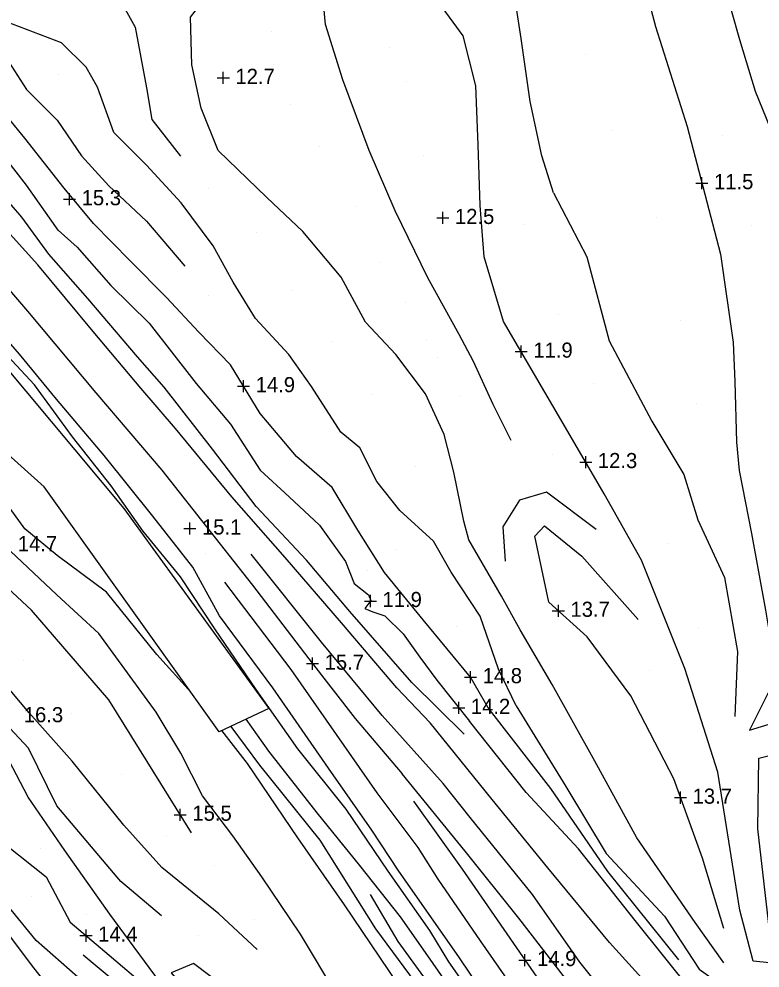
# Model space of a CAD drawing. Extents: x 2316231 to 2323598, y 363169 to 371906.
# Drawn here: x 2317584.1 to 2317829, y 368996.7 to 369310.4 of the extents above; entities that cross this region are included whole.
import ezdxf

# ---------------------------------------------------------------- set-up
doc = ezdxf.new("R2010")
doc.units = 0
for name, color, linetype in [('RD_DTM_BkLn1', 7, 'Continuous'), ('RD_DTM_Holes', 7, 'Continuous'), ('RD_DTM_Spot', 7, 'Continuous'), ('RD_DTM_Void', 7, 'Continuous'), ('RD_EX_H2O', 7, 'Continuous'), ('RD_EX_Road', 7, 'Continuous')]:
    doc.layers.add(name, color=color, linetype=linetype)

msp = doc.modelspace()

# ---------------------------------------------------------------- linework, layer by layer
at = {"layer": 'RD_DTM_BkLn1'}
for points in [[(2317782.837, 369460.705), (2317782.594, 369432.642), (2317782.438, 369391.736), (2317782.714, 369355.792), (2317786.981, 369336.313), (2317794.399, 369307.852), (2317804.873, 369274.863), (2317815.931, 369232.668), (2317820.146, 369203.448), (2317820.711, 369190.542), (2317821.19, 369170.485), (2317822.084, 369161.146), (2317826.2, 369140.318), (2317830.794, 369114.952), (2317834.404, 369093.232), (2317825.488, 369075.338), (2317850.452, 369082.918), (2317873.473, 369090.997)], [(2317760.77, 369252.893), (2317756.834, 369265.094), (2317753.065, 369283.07), (2317750.101, 369303.893), (2317745.612, 369332.635), (2317744.731, 369357.862), (2317746.292, 369377.559), (2317748.751, 369394.003), (2317748.589, 369406.502), (2317756.731, 369415.911)], [(2317749.221, 369201.912), (2317744.215, 369210.449), (2317737.856, 369231.761), (2317736.551, 369248.681), (2317735.802, 369268.773), (2317735.11, 369288.248), (2317730.903, 369304.793), (2317718.557, 369321.756), (2317712.857, 369334.049), (2317713.043, 369347.119), (2317712.64, 369364.808), (2317715.43, 369383.715), (2317719.945, 369391.379)], [(2317432.013, 369386.344), (2317442.486, 369375.124), (2317460.127, 369355.443), (2317478.446, 369335.774), (2317493.913, 369318.373), (2317510.005, 369300.102), (2317527.834, 369281.165), (2317547.605, 369259.096), (2317564.195, 369240.188), (2317586.899, 369213.855), (2317609.46, 369186.827), (2317631.28, 369161.237), (2317644.411, 369144.647), (2317661.326, 369123.263), (2317679.893, 369098.88), (2317695.188, 369079.236), (2317710.771, 369060.901)], [(2317603.388, 369234.989), (2317597.064, 369240.622), (2317586.563, 369255.484), (2317572.84, 369273.041), (2317557.863, 369287.639), (2317545.146, 369303.625), (2317558.121, 369313.62), (2317570.582, 369323.037), (2317588.942, 369336.266), (2317607.148, 369349.12), (2317627.756, 369363.021), (2317645.481, 369374.669), (2317656.957, 369379.9)], [(2317732.771, 369138.232), (2317731.078, 369144.425), (2317727.811, 369160.658), (2317724.628, 369173.086), (2317718.451, 369186.469), (2317708.67, 369199.452), (2317698.66, 369210.132), (2317690.619, 369225.079), (2317677.886, 369240.149), (2317666.024, 369251.417), (2317649.875, 369266.891), (2317644.354, 369280.88), (2317641.249, 369295.167), (2317640.768, 369310.985), (2317647.745, 369320.045), (2317658.722, 369332.777), (2317669.074, 369347.368), (2317677.092, 369358.284), (2317689.442, 369369.518), (2317696.262, 369379.988)], [(2317746.743, 369171.098), (2317740.844, 369182.992), (2317734.329, 369197.148), (2317729.589, 369206.155), (2317719.181, 369224.839), (2317708.439, 369246.95), (2317699.84, 369266.958), (2317691.105, 369290.222), (2317685.36, 369308.581), (2317683.507, 369328.587), (2317689.726, 369340.606), (2317697.767, 369357.685)], [(2317805.22, 369356.593), (2317814.174, 369332.04), (2317822.189, 369303.576), (2317827.399, 369286.514), (2317834.918, 369268.068), (2317842.317, 369242.711), (2317843.668, 369215.87), (2317847.498, 369190.663), (2317847.31, 369179.873), (2317846.989, 369166.565), (2317849.65, 369145.96), (2317853.827, 369120.823), (2317855.756, 369092.761)], [(2317615.349, 369320.71), (2317622.538, 369307.684), (2317626.274, 369287.565), (2317628.005, 369277.192), (2317637.437, 369264.981)], [(2317748.394, 369083.347), (2317742.612, 369095.562), (2317736.554, 369113.005), (2317726.955, 369127.589), (2317721.077, 369137.83), (2317709.969, 369147.923), (2317702.366, 369157.497), (2317696.765, 369168.663), (2317690.422, 369173.819), (2317680.723, 369188.899), (2317673.264, 369199.453), (2317662.284, 369211.336), (2317654.926, 369223.428), (2317648.284, 369235.439), (2317637.677, 369249.595), (2317626.236, 369262.092), (2317615.473, 369272.864), (2317610.108, 369287.845), (2317606.321, 369294.423), (2317598.162, 369302.538), (2317579.645, 369309.493)], [(2317577.553, 369300.902), (2317586.626, 369287.073), (2317596.699, 369276.967), (2317604.821, 369265.139), (2317613.769, 369255.232), (2317626.229, 369243.556), (2317638.967, 369228.677)], [(2317731.251, 369074.071), (2317713.952, 369091.122), (2317693.419, 369114.569), (2317679.145, 369131.535), (2317662.487, 369149.311), (2317648.027, 369168.187), (2317632.108, 369188.653), (2317623.262, 369198.719), (2317606.849, 369217.978), (2317593.926, 369232.696), (2317585.053, 369244.902), (2317571.27, 369260.744), (2317557.831, 369274.23), (2317544.007, 369289.202), (2317536.333, 369298.761)], [(2317662.831, 369002.833), (2317650.139, 369014.691), (2317631.297, 369029.928), (2317618.733, 369043.921), (2317601.682, 369065.097), (2317587.489, 369081.103), (2317567.834, 369104.294), (2317552.843, 369123.722), (2317535.639, 369145.548), (2317520.988, 369162.739), (2317509.946, 369176.071), (2317499.918, 369193.757), (2317485.99, 369211.355), (2317476.437, 369230.771), (2317464.626, 369241.934), (2317442.777, 369270.391), (2317423.581, 369291.314)], [(2317739.531, 369082.153), (2317733.331, 369092.858), (2317717.713, 369111.836), (2317704.937, 369127.487), (2317696.027, 369141.417), (2317687.585, 369155.577), (2317675.783, 369165.813), (2317663.855, 369179.982), (2317654.038, 369196.034), (2317643.547, 369206.863), (2317632.819, 369218.373), (2317620.891, 369230.485), (2317608.744, 369242.743), (2317599.033, 369254.408), (2317585.998, 369270.99), (2317575.151, 369284.186)], [(2317388.785, 369261.433), (2317411.96, 369230.758), (2317434.653, 369200.682), (2317451.495, 369177.81), (2317476.53, 369145.717), (2317500.032, 369113.761), (2317524.973, 369081.318), (2317539.886, 369060.985), (2317563.633, 369030.179), (2317588.855, 368996.846), (2317615.952, 368962.346), (2317639.468, 368931.079), (2317660.647, 368902.322), (2317686.777, 368868.534), (2317712.238, 368834.649), (2317734.89, 368804.943), (2317748.185, 368787.716), (2317777.485, 368748.886), (2317804.459, 368712.687)], [(2317760.77, 369252.893), (2317771.712, 369231.731), (2317779.087, 369204.035), (2317793.187, 369177.449), (2317803.814, 369159.857), (2317808.462, 369144.864), (2317817.231, 369125.779), (2317821.59, 369101.297), (2317820.677, 369079.863)], [(2317726.152, 368998.749), (2317719.87, 369009.191), (2317706.088, 369028.744), (2317692.179, 369049.245), (2317676.267, 369069.153), (2317662.47, 369088.813), (2317648.838, 369108.848), (2317637.531, 369126.013), (2317624.996, 369141.209), (2317614.577, 369156.121), (2317601.808, 369172.236), (2317589.202, 369189.463), (2317574.295, 369205.468), (2317561.605, 369220.681), (2317550.823, 369230.299), (2317542.236, 369240.456), (2317535.832, 369247.759)], [(2317631.197, 369014.042), (2317617.8, 369025.328), (2317596.628, 369050.394), (2317587.207, 369069.41), (2317579.555, 369077.649), (2317560.641, 369097), (2317544.822, 369118.017), (2317526.483, 369137.233), (2317511.259, 369151.419), (2317496.749, 369161.179), (2317480.142, 369182.24), (2317471.953, 369202.12), (2317480.097, 369201.251), (2317496.103, 369181.715), (2317510.156, 369158.15)], [(2317875.025, 369159.136), (2317877.216, 369130.751), (2317884.286, 369099.773), (2317887.499, 369077.387), (2317890.939, 369050.654), (2317892.28, 369037.767), (2317892.072, 369020.973), (2317865.295, 369009.189), (2317834.297, 368998.227), (2317826.722, 368999.043), (2317822.263, 369015.909), (2317815.09, 369061.486), (2317804.133, 369095.731), (2317789.806, 369131.557), (2317777.472, 369153.49), (2317763.205, 369178.024), (2317749.221, 369201.912)], [(2317641.102, 369041.466), (2317613.762, 369085.411), (2317588.219, 369115.047), (2317562.965, 369138.46), (2317547.884, 369155.684), (2317527.922, 369179.162), (2317512.433, 369195.146)], [(2317774.807, 369141.699), (2317758.375, 369153.961), (2317749.492, 369151.358), (2317743.955, 369142.578), (2317744.803, 369131.197)], [(2317817.014, 369009.849), (2317810.01, 369033.032), (2317800.455, 369059.212), (2317786.264, 369086.717), (2317771.887, 369106.226), (2317759.175, 369117.657), (2317754.598, 369139.466), (2317757.744, 369142.863), (2317770.082, 369132.891), (2317788.677, 369111.963)], [(2317817.026, 368998.497), (2317807.523, 369011.737), (2317788.284, 369039.735), (2317774.368, 369065.091), (2317760.249, 369090.483), (2317749.744, 369108.527), (2317743.512, 369119.601), (2317732.771, 369138.232)], [(2317689.123, 368987.856), (2317677.132, 369007.913), (2317664.395, 369026.86), (2317654.737, 369040.407), (2317644.72, 369053.691), (2317637.58, 369067.719), (2317629.418, 369081.342), (2317610.463, 369107.318), (2317596.644, 369120.124), (2317581.293, 369134.531)], [(2317733.184, 369046.471), (2317724.28, 369057.683), (2317704.173, 369080.181), (2317684.029, 369104.449), (2317660.825, 369133.525)], [(2317722.608, 369026.139), (2317716.048, 369036.54), (2317702.482, 369054.673), (2317683.245, 369082.258), (2317674.079, 369095.346), (2317652.144, 369124.216)], [(2317698.383, 369115.527), (2317701.074, 369114.431), (2317705.008, 369113.177), (2317711.046, 369107.201), (2317716.565, 369099.423), (2317722.23, 369091.864), (2317732.933, 369078.272)], [(2317620.371, 368966.337), (2317614.292, 368977.915), (2317603.509, 368993.706), (2317589.75, 369005.801), (2317573.207, 369026.067), (2317561.329, 369041.512), (2317550.377, 369057.726), (2317540.978, 369071.698), (2317529.435, 369089.843), (2317521.528, 369100.619), (2317511.955, 369106.614)], [(2317525.39, 369103.122), (2317531.465, 369105.975), (2317545.78, 369085.786), (2317562.213, 369062.196), (2317559.816, 369055.557), (2317567.264, 369044.634), (2317579.694, 369037.572), (2317593.058, 369026.903), (2317601.03, 369011.894), (2317613.916, 369000.946), (2317626.382, 368990.46), (2317627.136, 368983.836), (2317626.332, 368977.907), (2317630.113, 368969.116), (2317642.791, 368963.122)], [(2317748.394, 369083.347), (2317764.823, 369056.785), (2317778.147, 369034.596), (2317797.399, 369013.844), (2317808.85, 368996.392), (2317819.387, 368988.852), (2317829.096, 368989.803)], [(2317739.531, 369082.153), (2317759.698, 369056.06), (2317778.545, 369028.625), (2317802.063, 368999.507)], [(2317890.632, 369005.976), (2317857.36, 368993.809), (2317828.445, 368984.017), (2317815.219, 368983.956), (2317806.887, 368988.559), (2317787.699, 369012.486), (2317769.023, 369036.112), (2317751.729, 369054.741), (2317732.933, 369078.272), (2317732.896, 369078.01)], [(2317654.063, 369076.599), (2317663.628, 369063.822), (2317683.484, 369038.972), (2317701.9, 369009.694), (2317715.069, 368991.986), (2317743.672, 368951.059)], [(2317832.43, 369006.342), (2317828.265, 369042.76), (2317828.591, 369066.059), (2317844.99, 369070.317)], [(2317773.251, 368982.171), (2317749.291, 369013.226), (2317731.514, 369035.414), (2317710.771, 369060.901)], [(2317714.483, 369051.905), (2317730.563, 369029.367), (2317748.511, 369003.394), (2317766.447, 368977.552)], [(2317821.138, 368924.98), (2317816.918, 368934.779), (2317804.413, 368953.884), (2317788.409, 368975.037), (2317769.411, 368998.724), (2317753.832, 369021.08), (2317733.184, 369046.471)], [(2317800.727, 368903.713), (2317792.826, 368918.313), (2317776.996, 368942.903), (2317762.683, 368965.456), (2317751.265, 368984.698), (2317736.622, 369005.724), (2317722.608, 369026.139)], [(2317730.416, 368976.536), (2317709.444, 369005.555), (2317700.218, 369021.068)], [(2317624.831, 368977.295), (2317618.254, 368984.37), (2317616.503, 368991.59), (2317605.362, 369000.945)], [(2317782.634, 368912.285), (2317772.58, 368929.414), (2317757.573, 368954.011), (2317748.1, 368968.409), (2317736.828, 368983.58), (2317726.152, 368998.749)], [(2317737.77, 368869.106), (2317723.897, 368898.283), (2317703.183, 368930.003), (2317693.059, 368940.214), (2317679.208, 368960.063), (2317658.896, 368985.373), (2317641.778, 368998.255), (2317634.38, 368995.117), (2317638.619, 368990.269), (2317643.65, 368989.611), (2317654.667, 368974.625), (2317673.331, 368951.875), (2317690.394, 368927.962), (2317708.14, 368904.93), (2317724.626, 368882.176), (2317737.006, 368863.263), (2317755.071, 368835.864), (2317766.921, 368809.639)]]:
    msp.add_lwpolyline(points, dxfattribs=at)
at = {"layer": 'RD_DTM_Holes'}
msp.add_lwpolyline([(2317415.639, 369326.621), (2317407.693, 369340.894), (2317436.095, 369356.472), (2317529.833, 369254.93), (2317618.79, 369148.582), (2317666.685, 369082.56), (2317650.253, 369074.8), (2317592.402, 369155.739), (2317532.624, 369209.402), (2317463.423, 369289.005), (2317415.639, 369326.621)], dxfattribs=at)
at = {"layer": 'RD_DTM_Spot'}
for p, q in [((2317667.562, 369306.175), (2317667.562, 369306.175)), ((2317706.625, 369300.948), (2317706.625, 369300.948)), ((2317771.199, 369298.681), (2317771.199, 369298.681)), ((2317668.152, 369295.428), (2317668.152, 369295.428)), ((2317597.154, 369291.89), (2317597.154, 369291.89)), ((2317712.215, 369289.757), (2317712.215, 369289.757)), ((2317673.819, 369282.016), (2317673.819, 369282.016)), ((2317779.751, 369273.635), (2317779.751, 369273.635)), ((2317816.662, 369271.793), (2317816.662, 369271.793)), ((2317683.265, 369268.39), (2317683.265, 369268.39)), ((2317717.671, 369265.344), (2317717.671, 369265.344)), ((2317646.587, 369254.391), (2317646.587, 369254.391)), ((2317695.279, 369248.358), (2317695.279, 369248.358)), ((2317724.165, 369244.62), (2317724.165, 369244.62)), ((2317794.867, 369244.895), (2317794.867, 369244.895)), ((2317751.182, 369242.292), (2317751.182, 369242.292)), ((2317826.103, 369241.997), (2317826.103, 369241.997)), ((2317662.614, 369239.711), (2317662.614, 369239.711)), ((2317703.62, 369229.923), (2317703.62, 369229.923)), ((2317646.637, 369218.892), (2317646.637, 369218.892)), ((2317674.226, 369220.605), (2317674.226, 369220.605)), ((2317711.749, 369216.561), (2317711.749, 369216.561)), ((2317762.496, 369212.646), (2317762.496, 369212.646)), ((2317802.637, 369210.595), (2317802.637, 369210.595)), ((2317687.634, 369203.929), (2317687.634, 369203.929)), ((2317718.624, 369204.333), (2317718.624, 369204.333)), ((2317722.365, 369198.372), (2317722.365, 369198.372)), ((2317773.978, 369189.788), (2317773.978, 369189.788)), ((2317700.993, 369186.252), (2317700.993, 369186.252)), ((2317730.115, 369185.639), (2317730.115, 369185.639)), ((2317808.115, 369183.338), (2317808.115, 369183.338)), ((2317760.5, 369166.582), (2317760.5, 369166.582)), ((2317715.193, 369162.549), (2317715.193, 369162.549)), ((2317653.949, 369142.017), (2317653.949, 369142.017)), ((2317798.812, 369137.013), (2317798.812, 369137.013)), ((2317645.624, 369133.756), (2317645.624, 369133.756)), ((2317708.545, 369135.215), (2317708.545, 369135.215)), ((2317699.369, 369128.149), (2317699.369, 369128.149)), ((2317705.702, 369119.542), (2317705.702, 369119.542)), ((2317717.45, 369120.06), (2317717.45, 369120.06)), ((2317728.655, 369109.565), (2317728.655, 369109.565)), ((2317808.585, 369109.304), (2317808.585, 369109.304)), ((2317585.74, 369098.471), (2317585.74, 369098.471)), ((2317792.49, 369094.921), (2317792.49, 369094.921)), ((2317601.43, 369080.828), (2317601.43, 369080.828)), ((2317617.842, 369060.581), (2317617.842, 369060.581)), ((2317632.784, 369040.164), (2317632.784, 369040.164)), ((2317591.324, 369036.349), (2317591.324, 369036.349)), ((2317648.572, 369030.603), (2317648.572, 369030.603)), ((2317588.135, 369020.355), (2317588.135, 369020.355)), ((2317606.264, 369014.289), (2317606.264, 369014.289)), ((2317661.965, 369012.642), (2317661.965, 369012.642)), ((2317643.585, 369007.479), (2317643.585, 369007.479))]:
    msp.add_line(p, q, dxfattribs=at)
at = {"layer": 'RD_DTM_Void'}
for p, q in [((2317649.629, 369290.913), (2317653.629, 369290.913)), ((2317651.629, 369288.913), (2317651.629, 369292.913)), ((2317807.785, 369256.12), (2317811.785, 369256.12)), ((2317809.785, 369254.12), (2317809.785, 369258.12)), ((2317600.813, 369248.806), (2317600.813, 369252.806)), ((2317598.813, 369250.806), (2317602.813, 369250.806)), ((2317724.165, 369242.62), (2317724.165, 369246.62)), ((2317722.165, 369244.62), (2317726.165, 369244.62)), ((2317750.08, 369198.445), (2317750.08, 369202.445)), ((2317748.08, 369200.445), (2317752.08, 369200.445)), ((2317658.318, 369187.035), (2317658.318, 369191.035)), ((2317656.318, 369189.035), (2317660.318, 369189.035)), ((2317771.394, 369161.942), (2317771.394, 369165.942)), ((2317769.394, 369163.942), (2317773.394, 369163.942)), ((2317640.577, 369140.003), (2317640.577, 369144.003)), ((2317638.577, 369142.003), (2317642.577, 369142.003)), ((2317698.23, 369118.027), (2317702.23, 369118.027)), ((2317700.23, 369116.027), (2317700.23, 369120.027)), ((2317760.347, 369114.805), (2317764.347, 369114.805)), ((2317762.347, 369112.805), (2317762.347, 369116.805)), ((2317681.099, 369095.33), (2317681.099, 369099.33)), ((2317679.099, 369097.33), (2317683.099, 369097.33)), ((2317731.324, 369092.866), (2317735.324, 369092.866)), ((2317733.324, 369090.866), (2317733.324, 369094.866)), ((2317729.428, 369080.723), (2317729.428, 369084.723)), ((2317727.428, 369082.723), (2317731.428, 369082.723)), ((2317802.706, 369051.046), (2317802.706, 369055.046)), ((2317800.706, 369053.046), (2317804.706, 369053.046)), ((2317637.406, 369045.407), (2317637.406, 369049.407)), ((2317635.406, 369047.407), (2317639.406, 369047.407)), ((2317606.267, 369005.444), (2317606.267, 369009.444)), ((2317604.267, 369007.444), (2317608.267, 369007.444)), ((2317749.298, 368999.378), (2317753.298, 368999.378)), ((2317751.298, 368997.378), (2317751.298, 369001.378))]:
    msp.add_line(p, q, dxfattribs=at)
at = {"layer": 'RD_EX_H2O'}
for points in [[(2317603.388, 369234.989), (2317614.502, 369222.314), (2317627.121, 369209.835), (2317642.605, 369189.912), (2317654.056, 369176.452), (2317663.854, 369161.268), (2317673.393, 369152.488), (2317683.453, 369143.071), (2317691.988, 369131.032), (2317694.916, 369123.829), (2317699.591, 369120.102), (2317700.359, 369118.202), (2317698.383, 369115.527)], [(2317719.24, 369000.802), (2317710.209, 369013.624), (2317696.72, 369030.606), (2317682.595, 369048.054), (2317666.715, 369068.427), (2317659.169, 369079.01)], [(2317779.619, 368909.656), (2317770.442, 368924.698), (2317756.718, 368945.672), (2317744.98, 368965.394), (2317733.563, 368980.136), (2317719.24, 369000.802)]]:
    msp.add_lwpolyline(points, dxfattribs=at)
at = {"layer": 'RD_EX_Road'}
for points in [[(2317709.67, 369028.749), (2317700.691, 369042.25), (2317686.425, 369062.738), (2317668.006, 369089.387), (2317650.415, 369113.079), (2317641.525, 369129.163), (2317628.348, 369146.061), (2317612.216, 369166.139), (2317596.504, 369184.781), (2317584.23, 369199.64), (2317568.391, 369217.801), (2317551.407, 369237.088), (2317529.748, 369261.447), (2317509.712, 369283.959), (2317492.37, 369302.924), (2317480.167, 369316.799), (2317465.739, 369332.38), (2317451.162, 369348.122), (2317434.176, 369366.089), (2317422.97, 369378.407)], [(2317719.943, 369077.779), (2317708.957, 369089.366), (2317690.708, 369110.786), (2317672.108, 369132.384), (2317654.453, 369152.457), (2317635.782, 369175.088), (2317624.35, 369188.323), (2317608.619, 369207.142), (2317590.362, 369229.157), (2317572.905, 369248.344), (2317552.75, 369270.864), (2317532.495, 369293.868), (2317512.505, 369316.084), (2317506.343, 369322.88)], [(2317630.576, 368992.32), (2317614.166, 369014.565), (2317599.299, 369035.556), (2317587.154, 369053.216), (2317578.184, 369070.249), (2317564.228, 369083.884), (2317547.565, 369105.883), (2317532.299, 369123.648), (2317520.357, 369133.807), (2317501.363, 369142.15), (2317484.095, 369156.276), (2317469.357, 369178.009), (2317459.521, 369194.619), (2317463.157, 369203.598), (2317469.418, 369210.657), (2317469.317, 369221.73), (2317462.04, 369234.896), (2317450.557, 369250.627), (2317430.029, 369276.358), (2317413.559, 369294.878), (2317400.733, 369301.009), (2317383.05, 369307.947), (2317368.235, 369312.117), (2317357.467, 369320.915)], [(2317640.962, 369087.799), (2317629.708, 369100.304), (2317613.01, 369120.934), (2317596.761, 369133.12), (2317586.034, 369141.859), (2317576.249, 369155.306)], [(2317839.078, 368934.859), (2317832.09, 368944.01), (2317817.502, 368961.92), (2317801.462, 368980.638), (2317779.258, 369005.225), (2317758.916, 369029.91), (2317740.509, 369052.461), (2317719.943, 369077.779)], [(2317749.812, 368927.593), (2317745.765, 368936.439), (2317733.342, 368956.588), (2317722.21, 368970.452), (2317709.326, 368991.56), (2317691.677, 369017.605), (2317676.223, 369039.753), (2317659.59, 369064.288), (2317651.112, 369075.206)], [(2317786.898, 368914.25), (2317777.966, 368927.75), (2317761.032, 368953.492), (2317745.813, 368976.18), (2317729.456, 369000.474), (2317709.67, 369028.749)]]:
    msp.add_lwpolyline(points, dxfattribs=at)

# ---------------------------------------------------------------- texts
at = {"layer": 'RD_DTM_Void'}
for s, p in [('12.7', (2317655.629, 369288.913)), ('11.5', (2317813.785, 369254.12)), ('15.3', (2317604.813, 369248.806)), ('12.5', (2317728.165, 369242.62)), ('11.9', (2317754.08, 369198.445)), ('14.9', (2317662.318, 369187.035)), ('12.3', (2317775.394, 369161.942)), ('15.1', (2317644.577, 369140.003)), ('14.7', (2317583.712, 369134.479)), ('11.9', (2317704.23, 369116.027)), ('13.7', (2317766.347, 369112.805)), ('15.7', (2317685.099, 369095.33)), ('14.8', (2317737.324, 369090.866)), ('14.2', (2317733.428, 369080.723)), ('16.3', (2317585.699, 369077.973)), ('13.7', (2317806.706, 369051.046)), ('15.5', (2317641.406, 369045.407)), ('14.4', (2317610.267, 369005.444)), ('14.9', (2317755.298, 368997.378))]:
    msp.add_text(s, height=5, dxfattribs=at).set_placement(p)

doc.saveas('drawing.dxf')
